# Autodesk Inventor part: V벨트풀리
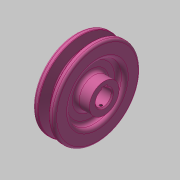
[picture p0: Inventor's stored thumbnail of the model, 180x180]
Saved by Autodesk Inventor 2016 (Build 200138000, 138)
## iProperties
Created: 2015-11
Part Number: V벨트풀리
Material: 강철, 탄소
Document SubType Name: Modeling
Designer: mduedu
Density: 1 g/cm^3
Appearance: 분홍색
Author: mduedu
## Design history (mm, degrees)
sketch "스케치1"
  geometry: L1 (-9.5, 0)-(9.5, 0); L2 (0, 0)-(0, 37.7); L3 (-4.825, 37.7)-(-9.5, 37.7); L4 (-9.5, 37.7)-(-9.5, 0); L5 (0, 28.7)-(-2.074, 28.7); L6 (-2.074, 28.7)-(-4.825, 37.7); L7 (4.825, 37.7)-(9.5, 37.7); L8 (9.5, 37.7)-(9.5, 0); L9 (0, 28.7)-(2.074, 28.7); L10 (2.074, 28.7)-(4.825, 37.7); L11 (-9.5, 35)-(9.5, 35); 3 further points
  constraints: 22 end point, 7 point on line, 4 perpendicular, 3 symmetric about line, 1 coincident, 1 horizontal, 1 horizontal alignment, 1 midpoint, 1 vertical
  dimensions: "d0" = 19 distance of L1.start L1.end; "d2" = 75.4 diameter of L2.end L1 (derived); "d3" = 34 deg angle of L10 L6; "d4" = 6.3 distance between parallel lines of L11 L9; "d5" = 2.7 distance between parallel lines of L7 L11; "d6" = 8 distance of point (4, 35) point (-4, 35); "d7" = 70 diameter of L11 L1
revolve "회전1" sketch "스케치1" stored, may be unused: angle "d8" = 90 deg
sketch "스케치2"
  geometry: C1 r 24 at (0, 0); C2 r 13 at (0, 0); 1 further point
  constraints: 2 centre point, 2 coincident
  dimensions: "d9" = 48 diameter of C1; "d10" = 26 diameter of C2
extrude "돌출1" cut sketch "스케치2" distance "d11" = 6; taper "d12" = 0 deg
extrude "돌출3" join sketch "스케치2" distance "d37" = 6; taper "d38" = 0 deg
fillet "모깎기1" dims "d13" = 3
fillet "모깎기2" dims "d14" = 3
fillet "모깎기3" dims "d15" = 1, "d16" = 0.5, "d17" = 2
hole "구멍1" diameter "d20" = 14; stored, may be unused: countersink angle "d24" = 90 deg, drill point angle "d26" = 118 deg; dims "d21" = 6, "d22" = 4, "d23" = 2, "d25" = 8, "d61" = 10, "d62" = 10
sketch "스케치3"
  geometry: L1 (-2.5, 0)-(2.5, 0); L2 (2.5, 0)-(2.5, 9.3); L3 (2.5, 9.3)-(-2.5, 9.3); L4 (-2.5, 9.3)-(-2.5, 0); 2 further points
  constraints: 8 end point, 2 parallel, 1 coincident, 1 horizontal, 1 midpoint, 1 perpendicular
  dimensions: "d27" = 5 distance of L2.end L3.end; "d29" = 9.3 distance of L3.end L1.start
extrude "돌출2" cut sketch "스케치3" stored distance "d30" = 6; taper "d31" = 0 deg
chamfer "모따기1" distance "d32" = 1; stored, may be unused: second distance "d33" = 2, angle "d34" = 45 deg
node "작업 평면1"
sketch "스케치4"
  geometry: L1 (19, -27)-(19, 27) reference; 2 further points
  constraints: 1 horizontal alignment
  dimensions: "d52" = 22 distance from line of L1 point (-3, 0)
hole "구멍2" sketch "스케치4" at (-3, 0) diameter "d42" = 2.459; stored, may be unused: countersink angle "d46" = 90 deg, drill point angle "d48" = 118 deg; dims "d43" = 6, "d44" = 4, "d45" = 2, "d47" = 8
chamfer "모따기3" distance "d58" = 1; stored, may be unused: second distance "d59" = 2, angle "d60" = 45 deg
node "솔리드1"
mirror "대칭1"
